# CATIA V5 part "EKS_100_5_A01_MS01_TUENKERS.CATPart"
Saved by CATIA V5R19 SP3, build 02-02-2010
Part number: EKS_100_5_A01_MS01_TUENKERS
Bounding box of the stored display mesh (mm): x -41.98 to 121.98, y -338.858 to 58.568, z -507.408 to 112.592
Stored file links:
  G:\Konstruktion\Modelle\Catia_V5\EKS_100_5_A01_MS01_TUENKERS.CATPart
  G:\Konstruktion\Modelle\Catia_V5\KS_100_2_S_A01_T12_TUENKERS.CATPart
  A01_SCHWENKTRAVERSE_233537_REV_001.CATPart
  C:\Dokumente und Einstellungen\mitric\Desktop\EKS_100.2_A01.CATPart
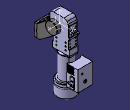
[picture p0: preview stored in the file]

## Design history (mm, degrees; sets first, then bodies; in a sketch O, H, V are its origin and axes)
AxisSystem1: origin (40, -178.8573, 10.5919), X (1, 0, 0), Y (0, 1, 0), Z (0, 0, 1)
Set1
  Point1: type Center, Curve edge [face of Solid2 | face of Solid2]
  Point2: type Center, Curve edge [face of Solid2 | face of Solid2]
  Point3: type Between, FirstPoint Point2, SecondPoint Point1, Ratio 0.5
Body1 "257084_Abdeckblech_EKS_100.2.1\\PartBody" (main body)
  Solid1: solid without history
Body2 "Drehbolzen.1\\PartBody"
  Solid2 "Solid.1": solid without history
Body3 "251774_Gehaeuse_EKS_100.2.1\\PartBody"
  Solid3 "Solid.1": solid without history
Body4 "Gehaeuse.1\\PartBody"
  Solid4 "Solid.1": solid without history
Body5 "Lagerschild IGK 90.1\\PartBody"
  Solid5 "Solid.1": solid without history
Body6 "Lagerschild.1\\PartBody"
  Solid6 "Solid.1": solid without history
Body7 "Lüfterhaube.1\\PartBody"
  Solid7 "Solid.1": solid without history
  Sketch1 "Sketch.6", origin (40, -118.9323, -505.4081), H (-1, 0, 0), V (0, 1, 0), geometry linked from another document
Body8 "Part6.1\\PartBody"
  Solid8 "Solid.1": solid without history
Body9 "Part6.2\\PartBody"
  Solid9 "Solid.1": solid without history
Body10 "Stopfen.1\\PartBody"
  Solid10 "Solid.1": solid without history
Body11 "Stopfen.2\\PartBody"
  Solid11 "Solid.1": solid without history
Body12 "Traegerplatte.1\\Traegerplatte.1\\PartBody"
  Solid12 "Solid.1": solid without history
Body13 "Motorsteuerung_MS01.1\\PartBody"
  Solid13 "Solid.1": solid without history
Body14 "Huelse.1\\PartBody"
  Solid14 "Solid.1": solid without history
Body15 "A01_SCHWENKTRAVERSE_233537_REV_001.1\\A01_SCHWENKTRAVERSE_233537"
  Solid15: solid without history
